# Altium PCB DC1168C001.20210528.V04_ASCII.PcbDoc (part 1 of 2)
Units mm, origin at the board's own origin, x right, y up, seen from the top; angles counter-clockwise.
Board outline 94.98 x 78.49 mm, 2 copper layers (Top Layer, Bottom Layer); 113 components, 100 nets, 347 pads, 214 vias.
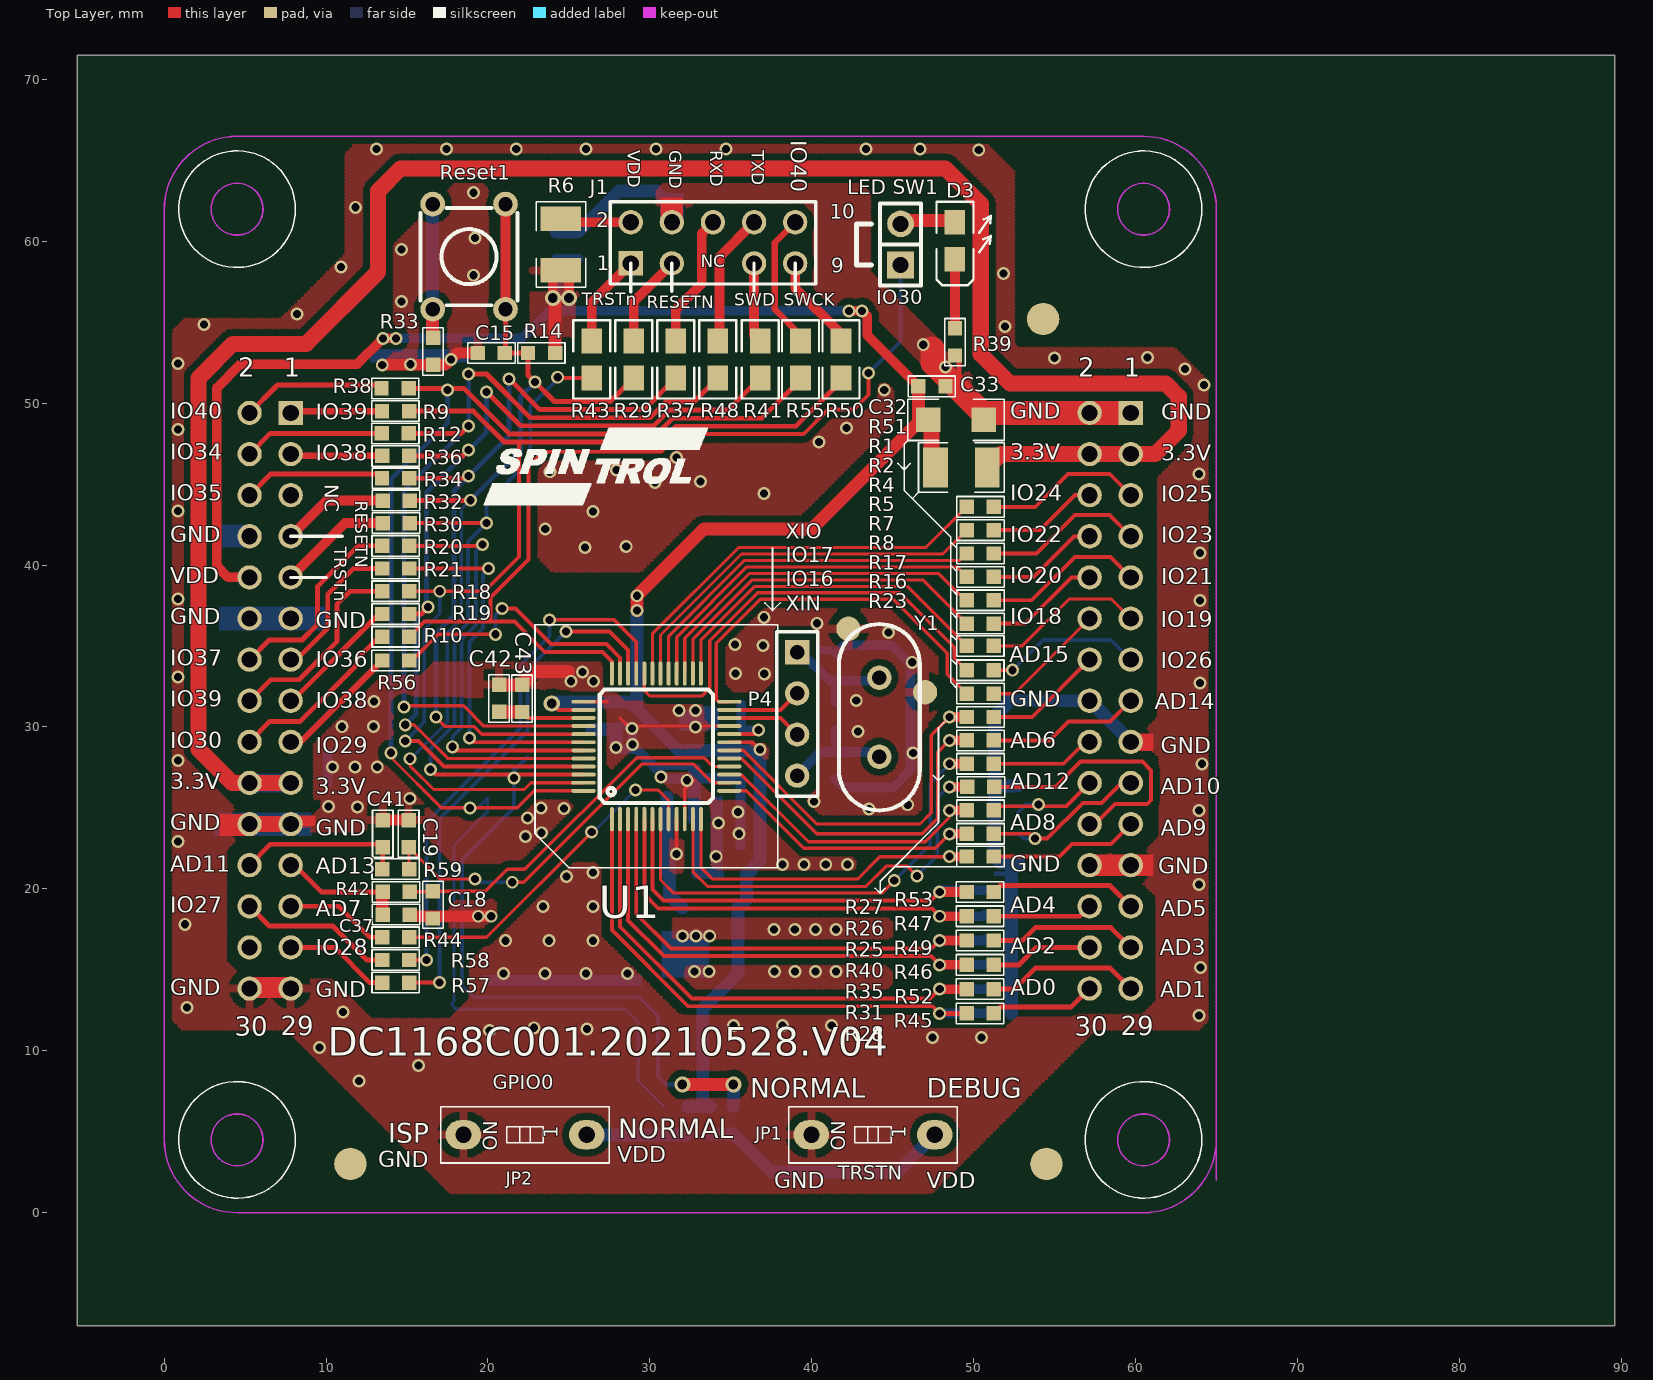
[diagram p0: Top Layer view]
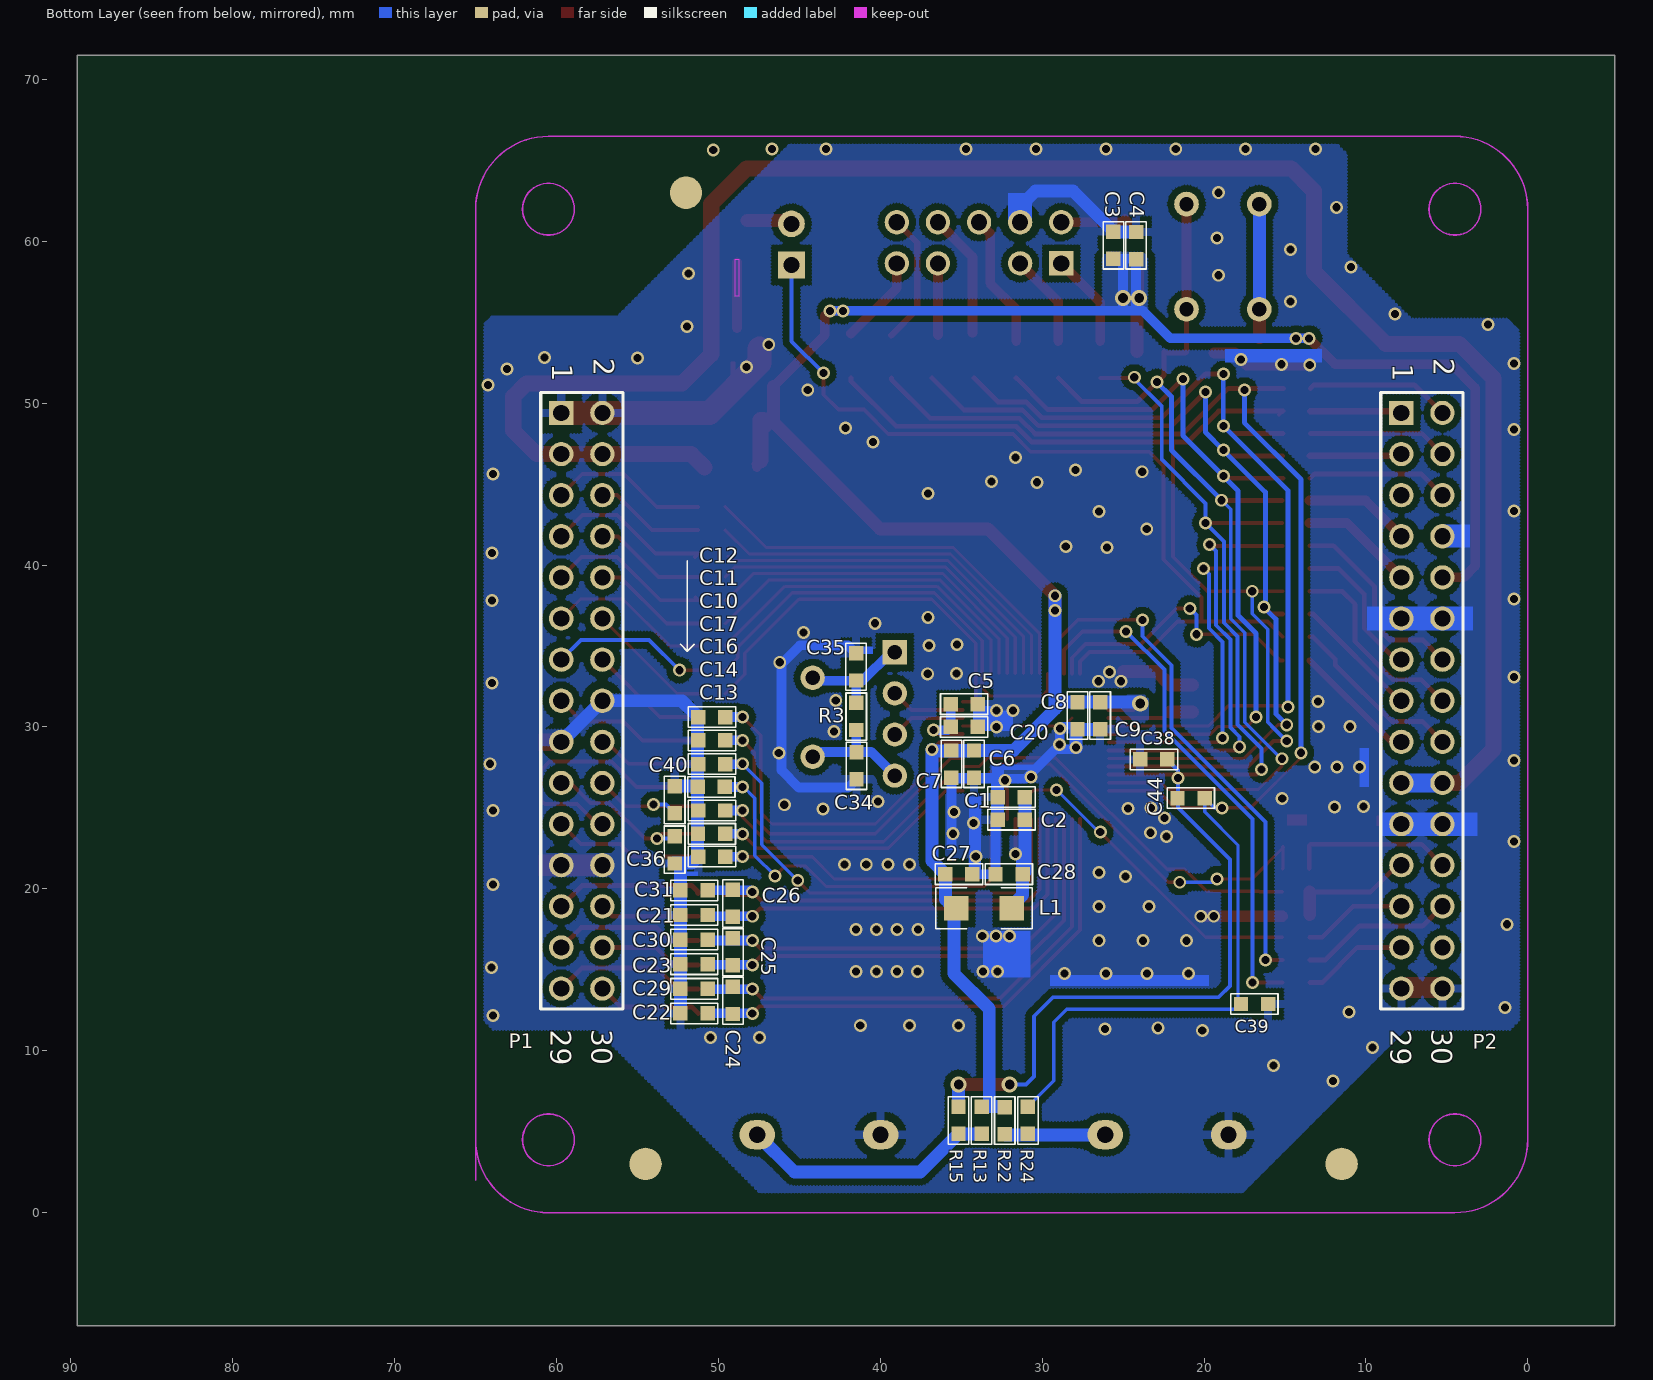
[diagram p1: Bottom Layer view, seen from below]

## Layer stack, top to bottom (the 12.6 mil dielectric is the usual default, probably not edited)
Top Solder: solder mask 0.0102, Solder Resist, Dk 3.5
Top Layer: signal copper 0.0356
Dielectric 1: dielectric 0.32, FR-4, Dk 4.8
Bottom Layer: signal copper 0.0356
Bottom Solder: solder mask 0.0102, Solder Resist, Dk 3.5

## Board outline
-5.372,-7 89.608,-7 89.608,71.49 -5.372,71.49

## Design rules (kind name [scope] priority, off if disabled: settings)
AssemblyTestPointUsage [All] p0: scope1count=1 scope1_0_kind=Board scope1_0_value=Board scope2count=1 scope2_0_kind=Board scope2_0_value=Board commentlength=0
AssemblyTestpoint [All] p0: scope1count=1 scope1_0_kind=Board scope1_0_value=Board scope2count=1 scope2_0_kind=Board scope2_0_value=Board commentlength=0
Clearance poly [All] p0 off: scope1count=1 scope1_0_kind=Board scope1_0_value=Board scope2count=1 scope2_0_kind=Board scope2_0_value=Board commentlength=48 gap=0.4 // Protel DXP Scope 2 Expression Was: InPolygon
Clearance xin [All] p0 off: scope1count=1 scope1_0_kind=Board scope1_0_value=Board scope2count=1 scope2_0_kind=Net scope2_0_value=XIN commentlength=48 gap=1 // Protel DXP Scope 1 Expression Was: InPolygon
Clearance xio [All] p0 off: scope1count=1 scope1_0_kind=Board scope1_0_value=Board scope2count=1 scope2_0_kind=Net scope2_0_value=XIO commentlength=48 gap=1 // Protel DXP Scope 1 Expression Was: InPolygon
Clearance [All] p0: scope1count=1 scope1_0_kind=Board scope1_0_value=Board scope2count=1 scope2_0_kind=Board scope2_0_value=Board commentlength=0 gap=0.2
Clearance poly [All vs InPolygon] p1: gap=0.4 ignorepadtopadclearanceinfootprint=FALSE except(0: Arc-Hole Track-Hole SMDPad-Hole THPad-Hole Via-Hole Fill-Hole Poly-Hole Region-Hole Text-Hole)
Clearance xio [InPolygon vs InNet('XIO')] p2: gap=1 ignorepadtopadclearanceinfootprint=FALSE except(0: Arc-Hole Track-Hole SMDPad-Hole THPad-Hole Via-Hole Fill-Hole Poly-Hole Region-Hole Text-Hole)
Clearance xin [InPolygon vs InNet('XIN')] p3: gap=1 ignorepadtopadclearanceinfootprint=FALSE except(0: Arc-Hole Track-Hole SMDPad-Hole THPad-Hole Via-Hole Fill-Hole Poly-Hole Region-Hole Text-Hole)
Clearance [All] p4: gap=0.2 ignorepadtopadclearanceinfootprint=FALSE except(0: Arc-Hole Track-Hole SMDPad-Hole THPad-Hole Via-Hole Fill-Hole Poly-Hole Region-Hole Text-Hole)
ComponentClearance [All] p0 off: scope1count=1 scope1_0_kind=Board scope1_0_value=Board scope2count=1 scope2_0_kind=Board scope2_0_value=Board commentlength=0 gap=0.254 collisioncheckmode=3
ComponentClearance [All] p1 off: gap=0.254 collisioncheckmode=3 verticalgap=0.254 showdistances=FALSE
DiffPairsRouting [All] p0: scope1count=1 scope1_0_kind=Board scope1_0_value=Board scope2count=1 scope2_0_kind=Board scope2_0_value=Board commentlength=0
DiffPairsRouting [All] p1: maxlimit=0.254 minlimit=0.24 mostfreqgap=0.254 toplayer_minwidth=0.2 toplayer_maxwidth=0.381 toplayer_prefwidth=5 bottomlayer_minwidth=0.2 bottomlayer_maxwidth=0.381 bottomlayer_prefwidth=5 maxuncoupledlength=12.7
FabricationTestPointUsage [All] p0: scope1count=1 scope1_0_kind=Board scope1_0_value=Board scope2count=1 scope2_0_kind=Board scope2_0_value=Board commentlength=0 valid=0 allowmultiple=FALSE
FabricationTestpoint [All] p0: scope1count=1 scope1_0_kind=Board scope1_0_value=Board scope2count=1 scope2_0_kind=Board scope2_0_value=Board commentlength=0 side=3 testpointundercomponent=TRUE minsize=1.016 maxsize=2.54 preferedsize=1.524 minholesize=0 maxholesize=1.016 preferedholesize=0.813 testpointgrid=0.025
FanoutControl Fanout_BGA [All] p0 off: scope1count=1 scope1_0_kind=Board scope1_0_value=Board scope2count=1 scope2_0_kind=Board scope2_0_value=Board commentlength=69 // Protel DXP Scope 1 Expression Was: IsBGA   Fanout_BGA (Default Rule)
FanoutControl Fanout_LCC [All] p0 off: scope1count=1 scope1_0_kind=Board scope1_0_value=Board scope2count=1 scope2_0_kind=Board scope2_0_value=Board commentlength=69 // Protel DXP Scope 1 Expression Was: IsLCC   Fanout_LCC (Default Rule)
FanoutControl Fanout_SOIC [All] p0 off: scope1count=1 scope1_0_kind=Board scope1_0_value=Board scope2count=1 scope2_0_kind=Board scope2_0_value=Board commentlength=71 // Protel DXP Scope 1 Expression Was: IsSOIC   Fanout_SOIC (Default Rule)
FanoutControl Fanout_Small [All] p0 off: scope1count=1 scope1_0_kind=Board scope1_0_value=Board scope2count=1 scope2_0_kind=Board scope2_0_value=Board commentlength=84 // Protel DXP Scope 1 Expression Was: (CompPinCount < 5)   Fanout_Small (Default Rule)
FanoutControl Fanout_Default [All] p0: scope1count=1 scope1_0_kind=Board scope1_0_value=Board scope2count=1 scope2_0_kind=Board scope2_0_value=Board commentlength=30 // Fanout_Default (Default Rule)
Height [All] p0 off: scope1count=1 scope1_0_kind=Board scope1_0_value=Board scope2count=1 scope2_0_kind=Board scope2_0_value=Board commentlength=0
Height [All] p1 off: minheight=0 maxheight=25.4 prefheight=12.7
HoleSize [All] p0: scope1count=1 scope1_0_kind=Board scope1_0_value=Board scope2count=1 scope2_0_kind=Board scope2_0_value=Board commentlength=0 absolutevalues=TRUE maxlimit=5 minlimit=0.025 maxpercent=80.000 minpercent=20.000
HoleSize [All] p1: absolutevalues=TRUE maxlimit=5 minlimit=0.025 maxpercent=80.000 minpercent=20.000
HoleToHoleClearance [All] p0 off: scope1count=1 scope1_0_kind=Board scope1_0_value=Board scope2count=1 scope2_0_kind=Board scope2_0_value=Board commentlength=0
HoleToHoleClearance [All] p1 off: gap=0.254 allowstackedmicrovias=FALSE
LayerPairs [All] p0: scope1count=1 scope1_0_kind=Board scope1_0_value=Board scope2count=1 scope2_0_kind=Board scope2_0_value=Board commentlength=0 enforce=FALSE
LayerPairs [All] p1: enforce=FALSE
MinimumSolderMaskSliver [All] p0 off: scope1count=1 scope1_0_kind=Board scope1_0_value=Board scope2count=1 scope2_0_kind=Board scope2_0_value=Board commentlength=0
MinimumSolderMaskSliver [All] p1 off: minsoldermaskwidth=0.254
NetAntennae [All] p0: scope1count=1 scope1_0_kind=Board scope1_0_value=Board scope2count=1 scope2_0_kind=Board scope2_0_value=Board commentlength=0
PasteMaskExpansion [All] p0 off: scope1count=1 scope1_0_kind=Board scope1_0_value=Board scope2count=1 scope2_0_kind=Board scope2_0_value=Board commentlength=0 expansion=0
PasteMaskExpansion [All] p1 off: expansion=0
PlaneClearance [All] p0: scope1count=1 scope1_0_kind=Board scope1_0_value=Board scope2count=1 scope2_0_kind=Board scope2_0_value=Board commentlength=0 clearance=0.508
PlaneConnect [All] p0: scope1count=1 scope1_0_kind=Board scope1_0_value=Board scope2count=1 scope2_0_kind=Board scope2_0_value=Board commentlength=0 planeconnectstyle=Direct reliefexpansion=0.508 reliefentries=4 reliefconductorwidth=0.254 reliefairgap=0.254
PlaneConnect [All] p1: planeconnectstyle=Direct reliefexpansion=0.508 reliefentries=4 reliefconductorwidth=0.254 reliefairgap=0.254
PolygonConnect [All] p0 off: scope1count=1 scope1_0_kind=Board scope1_0_value=Board scope2count=1 scope2_0_kind=Board scope2_0_value=Board commentlength=63 connectstyle=Relief reliefconductorwidth=0.5 reliefentries=4 polygonreliefangle="90 Angle" // Protel DXP Scope 2 Expression Was: (InPadClass('All Pads'))
PolygonConnect PolygonConnect_1 [All] p0: scope1count=1 scope1_0_kind=Board scope1_0_value=Board scope2count=1 scope2_0_kind=Board scope2_0_value=Board commentlength=0 connectstyle=Direct reliefconductorwidth=0.254 reliefentries=4 polygonreliefangle="90 Angle"
PolygonConnect [All vs (InPadClass('All Pads'))] p1: connectstyle=Relief reliefconductorwidth=0.5 reliefentries=4 polygonreliefangle="90 Angle" airgapwidth=0.5
PolygonConnect PolygonConnect_1 [All] p2: connectstyle=Direct reliefconductorwidth=0.254 reliefentries=4 polygonreliefangle="90 Angle" airgapwidth=0.254
RoutingCorners [All] p0: scope1count=1 scope1_0_kind=Board scope1_0_value=Board scope2count=1 scope2_0_kind=Board scope2_0_value=Board commentlength=0 cornerstyle=45-Degree minsetback=2.54 maxsetback=2.54
RoutingLayers [All] p0: scope1count=1 scope1_0_kind=Board scope1_0_value=Board scope2count=1 scope2_0_kind=Board scope2_0_value=Board commentlength=0 top layer=Automatic bottom layer=Automatic
RoutingPriority [All] p0: scope1count=1 scope1_0_kind=Board scope1_0_value=Board scope2count=1 scope2_0_kind=Board scope2_0_value=Board commentlength=0
RoutingTopology [All] p0: scope1count=1 scope1_0_kind=Board scope1_0_value=Board scope2count=1 scope2_0_kind=Board scope2_0_value=Board commentlength=0 topology=Shortest
RoutingVias [All] p0: scope1count=1 scope1_0_kind=Board scope1_0_value=Board scope2count=1 scope2_0_kind=Board scope2_0_value=Board commentlength=0 holewidth=0.8 width=0.5 viastyle="Through Hole" minholewidth=0.3 minwidth=0.3 maxholewidth=6 maxwidth=3
RoutingVias [All] p1: holewidth=0.8 width=0.5 viastyle="Through Hole" minholewidth=0.3 minwidth=0.3 maxholewidth=6 maxwidth=3
ShortCircuit [All] p0: scope1count=1 scope1_0_kind=Board scope1_0_value=Board scope2count=1 scope2_0_kind=Board scope2_0_value=Board commentlength=0 allowed=FALSE
SilkToBoardRegionClearance [All] p0 off: scope1count=1 scope1_0_kind=Board scope1_0_value=Board scope2count=1 scope2_0_kind=Board scope2_0_value=Board commentlength=0
SilkToBoardRegionClearance [All] p1 off:
SilkToSilkClearance [All] p0 off: scope1count=1 scope1_0_kind=Board scope1_0_value=Board scope2count=1 scope2_0_kind=Board scope2_0_value=Board commentlength=0
SilkToSilkClearance [All] p1 off: silktosilkclearance=0
SilkToSolderMaskClearance [All] p0 off: scope1count=1 scope1_0_kind=Board scope1_0_value=Board scope2count=1 scope2_0_kind=Board scope2_0_value=Board commentlength=44 // Protel DXP Scope 1 Expression Was: IsPad
SilkToSolderMaskClearance [IsPad] p1 off: minsilkscreentomaskgap=0 clearancetoexposedcopper=TRUE
SolderMaskExpansion [All] p0 off: scope1count=1 scope1_0_kind=Board scope1_0_value=Board scope2count=1 scope2_0_kind=Board scope2_0_value=Board commentlength=0 expansion=0.102
SolderMaskExpansion [All] p1 off: expansion=0.102 istentingtop=FALSE
UnRoutedNet [All] p0: scope1count=1 scope1_0_kind=Board scope1_0_value=Board scope2count=1 scope2_0_kind=Board scope2_0_value=Board commentlength=0
UnpouredPolygon [All] p0: scope1count=1 scope1_0_kind=Board scope1_0_value=Board scope2count=1 scope2_0_kind=Board scope2_0_value=Board commentlength=0
Width [All] p0: scope1count=1 scope1_0_kind=Board scope1_0_value=Board scope2count=1 scope2_0_kind=Board scope2_0_value=Board commentlength=0 maxlimit=5 minlimit=0.2 preferedwidth=0.24
Width [All] p1: maxlimit=5 minlimit=0.2 preferedwidth=0.24 minimp=50.000000 maximp=50.000000 favimp=50.000000
18 further rules are at their usual default settings.

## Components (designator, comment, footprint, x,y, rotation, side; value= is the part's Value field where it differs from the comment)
C1 "4.7uF/10V" 0603 31.91,25.662 r0 bottom
C2 "100nF" 0603 31.91,24.265 r0 bottom
C3 "100nF" 0603 25.596,59.76 r90 bottom
C4 "4.7uF/10V" 0603 24.196,59.735 r270 bottom
C5 "100nF" 0603 34.808,31.4 r180 bottom
C6 "4.7uF/10V" 0603 34.208,27.7 r270 bottom
C7 "100nF" 0603 35.608,27.7 r270 bottom
C8 "100nF" 0603 27.819,30.69 r270 bottom
C9 "4.7uF/10V" 0603 26.414,30.69 r270 bottom
C10 "100pF±10%" 0603 50.408,27.7 r0 bottom
C11 "100pF±10%" 0603 50.41,29.165 r0 bottom
C12 "100pF±10%" 0603 50.41,30.605 r0 bottom
C13 "100pF±10%" 0603 50.41,21.985 r0 bottom
C14 "100pF±10%" 0603 50.42,23.395 r0 bottom
C15 "1uF/6.3V" 0603 20.208,53.1 r180 top
C16 "100pF±10%" 0603 50.41,24.835 r0 bottom
C17 "100pF±10%" 0603 50.45,26.295 r0 bottom
C18 "100pF±10%" 0603 16.6,19 r270 top
C19 "100pF±10%" 0603 15.1,23.4 r90 top
C20 "4.7uF/10V" 0603 34.808,30 r180 bottom
C21 "100pF±10%" 0603 51.508,18.38 r0 bottom
C22 "100pF±10%" 0603 51.508,12.3 r0 bottom
C23 "100pF±10%" 0603 51.508,15.34 r0 bottom
C24 "22pF±10%" 0603 49.108,13.1 r90 bottom
C25 "22pF±10%" 0603 49.108,16.1 r90 bottom
C26 "22pF±10%" 0603 49.108,19.1 r90 bottom
C27 "100nF" 0603 35.146,20.9 r0 bottom
C28 "100nF" 0603 32.046,20.9 r180 bottom
C29 "100pF±10%" 0603 51.508,13.82 r0 bottom
C30 "100pF±10%" 0603 51.508,16.86 r0 bottom
C31 "100pF±10%" 0603 51.508,19.9 r0 bottom
C32 "47uF/10V" 1206 47.2,48.965 r0 top
C33 "100nF" 0603 47.43,51.04 r0 top
C34 "22pF不焊" 0603 41.466,27.605 r90 bottom
C35 "22pF不焊" 0603 41.496,33.705 r270 bottom
C36 "100pF±10%" 0603 52.7,22.4 r270 bottom
C37 "100pF±10%" 0603 14.33,18.4 r0 top
C38 "100nF" 0603 23.107,27.99 r0 bottom
C39 "100nF" 0603 16.88,12.88 r180 bottom
C40 "100pF±10%" 0603 52.7,25.5 r90 bottom
C41 "100pF±10%" 0603 13.5,23.4 r90 top
C42 "4.7uF/10V" 0603 20.69,31.77 r90 top
C43 "100nF" 0603 22.11,31.76 r90 top
C44 "4.7uF/10V" 0603 20.8,25.6 r180 bottom (schematic designator C4)
D3 "绿0805" led0805 48.85,60.025 r270 top
J1 "双排插针2.54*5" HDR2X5 28.82,58.635 r0 top locked
JP1 "DSIC01LH-P" S7.62*1 47.6,4.8 r180 top
JP2 "DSIC01LH-P" S7.62*1 26.1,4.8 r180 top
L1 "1.5uH" 1206 35.308,18.8 r180 bottom
"LED SW1" "单排插针2.54*2" CON2 45.49,58.535 r180 top
P1 "双排针2.54*15插针" HDR2X15 59.71,49.395 r270 bottom locked
P2 "双排针2.54*15插针" HDR2X15 7.81,49.395 r270 bottom locked
P4 "Header 4" HDR1X4 39.1,34.61 r270 top (schematic designator P1)
R1 "100R" 0603 50.41,43.595 r180 top
R2 "100R" 0603 50.41,42.152 r180 top
R3 "1M不焊" 0603 41.486,30.648 r90 bottom
R4 "100R" 0603 50.41,40.709 r180 top
R5 "100R" 0603 50.41,39.266 r180 top
R6 "0.1R  1/2W" 1210 24.508,58.2 r90 top
R7 "100R" 0603 50.41,37.824 r180 top
R8 "100R" 0603 50.41,36.381 r180 top
R9 "100R" 0603 14.288,49.51 r0 top
R10 "100R" 0603 14.31,35.569 r0 top
R12 "100R" 0603 14.268,48.13 r180 top
R13 "2k" 0603 33.74,5.7 r90 bottom
R14 "4.7K" 0603 23.308,53.1 r0 top
R15 "2K" 0603 35.17,5.7 r90 bottom
R16 "100R" 0603 50.408,33.5 r180 top
R17 "100R" 0603 50.408,35 r180 top
R18 "100R" 0603 14.31,38.377 r0 top
R19 "100R" 0603 14.31,36.973 r0 top
R20 "100R" 0603 14.31,41.186 r0 top
R21 "100R" 0603 14.31,39.782 r0 top
R22 "2k" 0603 32.31,5.675 r270 bottom
R23 "100R" 0603 50.41,32.052 r180 top
R24 "2K" 0603 30.88,5.7 r90 bottom
R25 "100R" 0603 50.41,27.724 r180 top
R26 "100R" 0603 50.41,29.166 r180 top
R27 "100R" 0603 50.41,30.609 r180 top
R28 "100R" 0603 50.41,21.995 r180 top
R29 "20R" 0805 29.008,52.7 r270 top
R30 "100R" 0603 14.328,42.59 r0 top
R31 "100R" 0603 50.41,23.398 r180 top
R32 "100R" 0603 14.328,43.98 r0 top
R33 "100R" 0603 16.608,53.2 r90 top
R34 "100R" 0603 14.288,45.36 r180 top
R35 "100R" 0603 50.41,24.845 r180 top
R36 "100R" 0603 14.308,46.74 r0 top
R37 "20R" 0805 31.608,52.7 r90 top
R38 "100R" 0603 14.258,50.91 r180 top
R39 "1k" 0603 48.85,53.78 r90 top
R40 "100R" 0603 50.45,26.295 r180 top
R41 "20R" 0805 36.808,52.7 r270 top
R42 "100R" 0603 14.33,19.807 r0 top
R43 "20R" 0805 26.408,52.7 r270 top
R44 "100R" 0603 14.308,17 r0 top
R45 "100R" 0603 50.408,12.3 r0 top
R46 "100R" 0603 50.408,15.3 r0 top
R47 "100R" 0603 50.408,18.3 r0 top
R48 "20R" 0805 34.208,52.7 r90 top
R49 "100R" 0603 50.408,16.8 r0 top
R50 "20R" 0805 41.808,52.7 r270 top
R51 "0.1R 1/2W" 1210 50.85,46.025 r180 top (schematic designator R39)
R52 "100R" 0603 50.408,13.8 r0 top
R53 "100R" 0603 50.408,19.8 r0 top
R55 "20R" 0805 39.308,52.7 r90 top
R56 "100R" 0603 14.3,34.1 r0 top
R57 "100R" 0603 14.308,14.2 r0 top
R58 "100R" 0603 14.308,15.6 r0 top
R59 "100R" 0603 14.308,21.21 r0 top
Reset1 "插件按键6*6*5" SW-TACT-6X6 18.833,59.048 r270 top
U1 "SPC1168" PQFP48 30.408,28.8 r90 top locked
Y1 "OSC32MHz不焊" OSC 44.176,30.595 r90 top locked

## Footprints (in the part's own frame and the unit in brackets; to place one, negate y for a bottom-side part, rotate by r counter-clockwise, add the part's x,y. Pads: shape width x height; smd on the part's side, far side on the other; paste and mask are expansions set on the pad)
0603 [mil]
  rect 35x35 smd: 1(-33,0) 2(33,0)
  silkscreen extent -58,-25 57,25
0805 [mil]
  rect 60x50 smd: 1(-45,0) 2(45,0)
  silkscreen extent -95,-45 95,45
1206 [mil]
  rect 60x60 smd: 1(0,0) 2(135,0)
  silkscreen extent -50,-50 185,50
1210 [mm]
  rect 1.524x2.5 smd: 1(0,0) 2(3.2,0)
  silkscreen extent -1.05,-1.53 4.25,1.53
CON2 [mil]
  rect 65x65 hole 39.37: 1(0,0)
  round 65 hole 39.37: 2(0,-100)
  silkscreen extent -50,-150 50,50
HDR1X4 [mm] "Connector; Header; 4 Position"
  rect 1.5x1.5 hole 0.9: 1(0,0)
  round 1.5 hole 0.9: 2(2.54,0) 3(5.08,0) 4(7.62,0)
  silkscreen extent -1.27,-1.27 8.89,1.27
HDR2X5 [mm] "Connector; Header; 5x2 Position"
  rect 1.5x1.5 hole 1: 1(0,0)
  round 1.5 hole 1: 2(0,2.54) 3(2.54,0) 4(2.54,2.54) 6(5.08,2.54) 7(7.62,0) 8(7.62,2.54) 9(10.16,0) 10(10.16,2.54)
  silkscreen extent -1.27,-1.27 11.43,3.81
HDR2X15 [mm] "Connector; Header; 15x2 Position"
  rect 1.5x1.5 hole 1: 1(0,0)
  round 1.5 hole 1: 2(0,2.54) 3(2.54,0) 4(2.54,2.54) 5(5.08,0) 6(5.08,2.54) 7(7.62,0) 8(7.62,2.54) 9(10.16,0) 10(10.16,2.54) 11(12.7,0) 12(12.7,2.54) 13(15.24,0) 14(15.24,2.54) 15(17.78,0) 16(17.78,2.54) 17(20.32,0) 18(20.32,2.54) 19(22.86,0) 20(22.86,2.54) 21(25.4,0) 22(25.4,2.54) 23(27.94,0) 24(27.94,2.54) 25(30.48,0) 26(30.48,2.54) 27(33.02,0) 28(33.02,2.54) 29(35.56,0) 30(35.56,2.54)
  silkscreen extent -1.27,-1.27 36.83,3.81
led0805 [mil]
  rect 60x50 smd: 1(-45,0) 2(45,0)
  Bottom Layer keep-out region: 134.82,-4.48 134.82,4.38 44.82,4.38 44.82,-4.48
  silkscreen extent -95,-45 108,88
OSC [mm] "CRYSTAL 32.0000MHZ 20PF T/H"
  round 1.5 hole 0.9: 1(-2.44,0) 2(2.44,0)
  silkscreen extent -5.75,-2.5 5.75,2.5
PQFP48 [mm]
  oval 1.5x0.24 smd: 1(-4.5,2.75) 2(-4.5,2.25) 3(-4.5,1.75) 4(-4.5,1.25) 5(-4.5,0.75) 6(-4.5,0.25) 7(-4.5,-0.25) 8(-4.5,-0.75) 9(-4.5,-1.25) 10(-4.5,-1.75) 11(-4.5,-2.25) 12(-4.5,-2.75) 25(4.5,-2.75) 26(4.5,-2.25) 27(4.5,-1.75) 28(4.5,-1.25) 29(4.5,-0.75) 30(4.5,-0.25) 31(4.5,0.25) 32(4.5,0.75) 33(4.5,1.25) 34(4.5,1.75) 35(4.5,2.25) 36(4.5,2.75)
  oval 0.24x1.5 smd: 13(-2.75,-4.5) 14(-2.25,-4.5) 15(-1.75,-4.5) 16(-1.25,-4.5) 17(-0.75,-4.5) 18(-0.25,-4.5) 19(0.25,-4.5) 20(0.75,-4.5) 21(1.25,-4.5) 22(1.75,-4.5) 23(2.25,-4.5) 24(2.75,-4.5) 37(2.75,4.5) 38(2.25,4.5) 39(1.75,4.5) 40(1.25,4.5) 41(0.75,4.5) 42(0.25,4.5) 43(-0.25,4.5) 44(-0.75,4.5) 45(-1.25,4.5) 46(-1.75,4.5) 47(-2.25,4.5) 48(-2.75,4.5)
  silkscreen extent -7.5,-7.5 7.5,7.5
S7.62*1 [mm]
  oval 2.2x1.8 hole 1: 1(0,0) 2(7.62,0)
  silkscreen extent -1.4,-1.74 9.02,1.74
SW-TACT-6X6 [mil]
  round 60 hole 35: 1(-127.95,88.58) 1(127.95,88.58) 2(-127.95,-88.58) 2(127.95,-88.58)
  silkscreen extent -118,-118 118,118

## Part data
C1 C2 C4 C5 C6 C7 C8 C9 C10 C11 C12 C13 C14 C16 C17 C18 C19 C20 C21 C22 C23 C24 C25 C26 C29 C30 C31 C36 C37 C38 C39 C40 C41 C42 C43 C44: library part CAP-CC(SMD), "Capacitor"
C3: library part CAP-CC, "Capacitor"
C15 C32 C33: library part Cap, "Capacitor"
C27 C28: library part CAP-CC
C34 C35: library part "Capacitor Unpolarized", "CAP CER 20PF 10V X7R 0603"
D3: library part LED2, "FC-2012UGK-520D5"
J1: library part CON10_BI, "ISP SOCKET"
JP1 JP2: library part SW-2
L1: library part INDUCTOR1
"LED SW1": library part Jumper, "Jumper Wire"
P1 P2: library part "Header 15X2", "Header, 15-Pin, Dual row"
P4: "Header, 4-Pin"
R1 R2 R4 R5 R6 R7 R8 R9 R10 R12 R15 R16 R17 R18 R19 R20 R21 R23 R24 R25 R26 R27 R28 R29 R30 R31 R32 R34 R35 R36 R37 R38 R40 R41 R42 R43 R44 R45 R46 R47 R48 R49 R50 R51 R52 R53 R55 R56 R57 R58 R59: library part RES(SMD)
R3: library part Resistor, "Resistor"
R13 R14 R22 R33 R39: library part Res1, "Resistor"
Reset1: library part SW-PB, "Switch"
U1: library part GECKO, "32-bit ARM CM4 MCU"
Y1: library part OSC32MHz, "CRYSTAL 32.0000MHZ 20PF T/H"

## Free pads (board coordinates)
  round 2 smd: 1(11.5,3) 1(54.3,55.2) 1(54.5,3)
  round 2 smd far side: 1(11.5,3) 1(52,63) 1(54.5,3)
  round 1.5 smd: 1(47,32.14) 2(42.27,36.06)

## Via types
v1: diameter 0.8, hole 0.5, Top Layer to Bottom Layer, tented both sides, 209 vias
v2: diameter 1, hole 0.6, Top Layer to Bottom Layer, tented both sides, 5 vias

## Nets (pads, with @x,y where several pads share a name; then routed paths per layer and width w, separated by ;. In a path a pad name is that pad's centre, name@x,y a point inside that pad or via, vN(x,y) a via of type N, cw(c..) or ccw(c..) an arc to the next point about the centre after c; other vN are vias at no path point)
+3.3V: P1.3 P1.4 P2.19 P2.20 R51.1 | length 127
  Top Layer w1: P2.19@7.81,26.535 P2.20@5.27,26.535 4.2,26.535 2.118,28.617 2.118,51.54 4.238,53.66 8.768,53.66 13.208,58.1 13.208,63.1 14.608,64.5 48.25,64.5 50.44,62.31 50.44,53.02 52.24,51.22 61.855,51.22 62.67,50.405 62.67,48.305 61.22,46.855 P1.3@59.71,46.855 P1.4@57.17,46.855 51.68,46.855 R51.1@50.85,46.025
  Bottom Layer w1.2: P2.20@5.27,26.535 P2.19@7.81,26.535
ADC6: C10.1 R25.2 U1.7 | length 29.7
  Top Layer w0.2: U1.7@30.658,24.3 30.658,20.54 31.468,19.73 44.33,19.73 v1(45.1,20.5)
  Top Layer w0.6: v1@48.424,27.724 v1(48.51,27.724) R25.2@49.572,27.724
  Bottom Layer w0.2: v1(45.1,20.5) 47.33,22.73 47.33,26.52 v1@48.51,27.7
  Bottom Layer w0.6: v1@48.51,27.7 C10.1@49.57,27.7
ADC7: R44.2 U1.8 | length 21.2
  Top Layer w0.2: R44.2@15.146,17 19.908,17 v1(26.408,23.5) ; v1(29.108,26.1) 30.508,26.1 31.158,25.45 U1.8@31.158,24.3
  Bottom Layer w0.2: v1@26.458,23.45 v1(29.108,26.1)
ADC8: C17.1 R40.2 U1.11 | length 26.9
  Top Layer w0.2: U1.11@32.658,24.3 32.658,21.06 33.578,20.14 43.34,20.14 44.6,21.4 45.9,21.4 v1(46.5,20.8)
  Top Layer w0.6: v1@48.448,26.295 R40.2@49.612,26.295
  Bottom Layer w0.2: v1(46.5,20.8) 47.75,22.05 47.75,25.587 v1@48.448,26.285
  Bottom Layer w0.6: v1@48.448,26.285 C17.1@49.612,26.285
  other v1: 48.51,26.28
ADC9: C13.1 R28.2 U1.12 | length 21.8
  Top Layer w0.2: U1.12@33.158,24.3 33.158,21.32 33.878,20.6 42.828,20.6 44.208,21.98 v1@48.408,21.98 ; R28.2@49.267,22.3 R28.2@49.572,21.995
  Top Layer w0.6: v1@48.408,21.98 R28.2@49.557,21.98
  Bottom Layer w0.6: v1@48.408,21.985 C13.1@49.572,21.985
  other v1: 48.51,21.98
ADC10: C14.1 R31.2 U1.13 | length 17.7
  Top Layer w0.2: U1.13@34.908,26.05 35.95,26.05 39.5,22.5 47.62,22.5 v1@48.518,23.398
  Top Layer w0.6: v1@48.518,23.398 R31.2@49.572,23.398
  Bottom Layer w0.6: v1@48.418,23.395 C14.1@49.582,23.395
  other v1: 48.51,23.39
ADC11: C19.1 R59.2 U1.14 | length 25.7
  Top Layer w0.2: C19.1@15.1,22.562 C19.1@15.116,22.546 ; C19.1@15.116,22.62 C19.1@15.116,22.546 ; R59.2@15.146,21.23 15.116,21.26 C19.1@15.116,22.546 ; C19.1@15.146,22.6 C19.1@15.146,22.516 ; v1(19.2,20.6) 17.062,20.6 C19.1@15.146,22.516 ; v1(21.5,20.4) 22.2,20.4 29.5,27.7 32.7,27.7 33.85,26.55 U1.14@34.908,26.55 ; C19.1@15.116,22.546 C19.1@15.146,22.516
  Bottom Layer w0.2: v1(19.2,20.6) 19.4,20.4 v1(21.5,20.4)
ADC12: C16.1 R35.2 U1.15 | length 18.6
  Top Layer w0.2: U1.15@34.908,27.05 35.65,27.05 39.8,22.9 47.01,22.9 48.51,24.4 v1(48.51,24.83)
  Top Layer w0.6: v1(48.51,24.83) 48.525,24.845 R35.2@49.572,24.845
  Bottom Layer w0.6: v1@48.408,24.835 C16.1@49.572,24.835
ADC13: C18.1 R42.2 U1.16 | length 23.4
  Top Layer w0.2: R42.2@15.168,19.807 16.569,19.807 C18.1@16.6,19.838 19.838,19.838 21.2,21.2 22.282,21.2 29.182,28.1 33.35,28.1 33.9,27.55 U1.16@34.908,27.55
ADC14: C11.1 R26.2 U1.17 | length 22.5
  Top Layer w0.2: U1.17@34.908,28.05 35.65,28.05 40.3,23.4 46.83,23.4 47.78,24.35 47.78,28.436 v1(48.51,29.166)
  Top Layer w0.6: v1(48.51,29.166) R26.2@49.572,29.166 R26.2@49.658,29.166
  Bottom Layer w0.6: v1(48.51,29.166) C11.1@49.57,29.166
ADC15: C12.1 R27.2 U1.18 | length 23.2
  Top Layer w0.2: U1.18@34.908,28.55 35.758,28.55 40.308,24 46.69,24 47.38,24.69 47.38,29.47 v1(48.51,30.6)
  Top Layer w0.6: v1@48.51,30.609 R27.2@49.572,30.609
  Bottom Layer w0.6: v1@48.408,30.605 C12.1@49.572,30.605
ADC_7: P2.25 R44.1 | length 6.5
  Top Layer w0.3: P2.25@7.81,18.915 10.793,18.915 12.708,17 R44.1@13.47,17
ADC_11: C41.1 P2.24 R59.1 | length 10.2
  Top Layer w0.3: P2.24@5.27,21.455 6.56,22.745 13.417,22.745 13.5,22.662 R59.1@13.5,21.24
ADC_13: C37.1 P2.23 R42.1 | length 7.8
  Top Layer w0.3: P2.23@7.81,21.455 8.053,21.455 9.701,19.807 13.47,19.807 R42.1@13.492,19.807 ; C37.1@13.47,18.4 C37.1@13.492,18.422
  Top Layer w0.8: C37.1@13.47,18.4 R42.1@13.47,19.807
DC_BUS: P1.18 R25.1 | length 6.2
  Top Layer w0.24: R25.1@51.248,27.724 55.549,27.724 P1.18@56.9,29.075
DIR: P1.11 R17.1 | length 10.2
  Top Layer w0.2: R17.1@51.246,35 53.008,35 55.908,37.9 58.505,37.9 P1.11@59.71,36.695
GND: C1.2 C2.2 C3.2 C4.1 C5.2 C6.2 C7.2 C8.2 C9.2 C10.2 C11.2 C12.2 C13.2 C14.2 C15.2 C16.2 C17.2 C18.2 C19.2 C20.2 C21.2 C22.2 C23.2 C27.1 C28.1 C29.2 C30.2 C31.2 C32.2 C33.2 C34.1 C35.1 C36.2 C37.2 C38.2 C39.2 C40.2 C41.2 C42.2 C43.2 J1.4 JP1.2 JP2.2 P1.1 P1.2 P1.16 P1.17 P1.23 P1.24 P2.8 P2.11 P2.12 P2.21 P2.22 P2.29 P2.30 pad.1@47,32.14 pad.2 R33.1 R39.1 U1.10 U1.21 U1.37 | length 125.8
  Top Layer w0.2: 28.158,30.55 28.658,30.05 U1.21@34.908,30.05
  Top Layer w0.24: U1.37@25.908,31.55 27.37,31.55 ; U1.10@32.158,24.3 32.158,26.15 32.708,26.7
  Top Layer w0.7: P2.21@7.81,23.995 P2.21@7.815,24 ; v1(13.47,52.362) R33.1@16.608,52.362 17.37,52.362 v1(17.708,52.7) 18.108,53.1 C15.2@19.37,53.1 ; C37.2@15.168,18.3 v1(20.2,18.3)
  Top Layer w0.8: C42.2@20.7,32.598 C43.2@22.11,32.598 22.932,33.42 24.98,33.42
  Top Layer w1: P2.22@5.27,23.995 P2.21@7.81,23.995
  Top Layer w1.5: 47.46,53.36 47.46,52.487 50.552,49.395 P1.2@57.17,49.395 P1.1@59.71,49.395
  Bottom Layer w0.6: v1@27.819,28.611 v1@28.908,28.611 ; v1(28.908,29.9) v1@28.908,28.611 ; C2.2@32.748,24.265 32.884,24.129 C28.1@32.884,20.9 C27.1@34.308,20.9 ; 32.77,26.862 C6.2@34.208,26.862 C7.2@35.608,26.862 35.546,26.8 32.748,26.8 31.008,26.8 29.197,28.611 v1@28.908,28.611 ; v1(32.808,31) C5.2@33.57,31 ; C20.2@33.97,30 C5.2@33.97,31 ; C34.1@41.466,26.767 41.973,26.26 45.038,26.26 46.103,27.325 46.103,33.887 44.956,35.035 41.987,35.035 C35.1@41.496,34.543
  Bottom Layer w0.8: C4.1@24.196,60.573 25.571,60.573 C3.2@25.596,60.599 28.097,63.1 30.408,63.1 31.36,62.148 J1.4@31.36,61.175 ; C9.2@26.414,29.852 C8.2@27.819,29.852 ; v1(27.908,28.73) C8.2@27.908,29.841 ; C2.2@32.748,24.265 C1.2@32.748,25.662 32.748,26.8 ; C13.2@51.248,21.985 51.633,21.6 C36.2@52.346,21.6 ; C13.2@51.288,22.025 C17.2@51.288,26.295 51.288,30.565 C12.2@51.248,30.605 52.258,31.615 P1.16@57.17,31.615 P1.17@59.71,29.075 ; C17.2@51.331,26.338 C40.2@52.7,26.338 ; C22.2@52.346,12.3 C29.2@52.346,13.82 C23.2@52.346,15.34 C30.2@52.346,16.86 C21.2@52.346,18.38 C31.2@52.346,19.9 C36.2@52.346,21.6 ; C36.2@52.8,21.6 C36.2@52.346,21.6
  other v1: 12.04,8.125 15.71,9.075 9.598,10.2 47.464,10.81 50.498,10.81 20.107,11.24 26.118,11.33 22.848,11.41 35.168,11.55 38.202,11.55 41.236,11.55 63.93,12.175 11.04,12.375 1.41,12.665 20.968,14.77 23.518,14.77 26.068,14.77 28.618,14.77 32.748,14.89 33.648,14.89 37.708,14.89 38.974,14.89 40.241,14.89 41.507,14.89 64.008,15.14 21.088,16.79 23.778,16.79 26.488,16.79 32.018,17.07 32.858,17.07 33.698,17.07 37.678,17.49 38.954,17.49 40.231,17.49 41.507,17.49 1.29,17.805 19.4,18.3 23.408,18.9 26.488,18.9 63.938,20.27 24.848,20.76 26.488,21.01 38.2,21.499 39.533,21.499 40.867,21.499 42.2,21.499 34.1,22 0.848,22.92 22.318,23.22 35.5,23.4 23.307,23.46 34.248,24.06 22.438,24.37 35.448,24.73 63.93,24.844 43.55,24.93 24.708,24.95 23.278,24.99 11.938,25.05 10.138,25.08 45.93,25.19 40.13,25.39 15.17,25.58 32.3,26.7 30.7,26.9 10.398,27.53 11.779,27.53 13.16,27.53 64.118,27.72 0.848,27.92 46.27,28.39 28.918,28.9 42.86,29.72 10.99,30.01 32.808,30 12.93,30.03 31.808,31 12.96,31.56 42.75,31.62 63.978,32.72 25.118,32.82 26.507,32.82 0.848,33.07 37.07,33.28 35.29,33.3 25.838,33.38 46.21,33.99 36.99,35.03 35.27,35.08 44.74,35.82 40.33,36.4 37.05,36.77 63.998,37.81 0.848,37.912 63.978,40.73 25.998,41.09 28.54,41.15 23.538,42.22 26.5,43.3 0.848,43.33 37.05,44.42 30.307,45.11 33.12,45.16 63.918,45.63 23.818,45.76 27.938,45.88 31.648,46.63 40.448,47.59 0.848,48.37 42.15,48.47 44.48,50.81 64.238,51.11 63.06,52.12 48.27,52.23 15.208,52.4 0.848,52.44 54.99,52.79 60.75,52.83 46.89,53.61 51.95,54.73 2.458,54.85 8.208,55.5 14.67,56.28 19.107,57.9 51.85,58.02 10.908,58.4 14.67,59.499 19.2,60.2 11.808,62.1 19.107,63 50.32,65.64 46.7,65.699 13.11,65.71 17.429,65.71 21.748,65.71 26.067,65.71 30.386,65.71 34.704,65.71 43.342,65.71
GPIO16: P4.3 U1.22 | length 4.6
  Top Layer w0.24: U1.22@34.908,30.55 38.08,30.55 P4.3@39.1,29.53
GPIO17: P4.2 U1.23 | length 4.6
  Top Layer w0.24: U1.23@34.908,31.05 38.08,31.05 P4.2@39.1,32.07
GPIO18: R23.2 U1.24 | length 24.1
  Top Layer w0.2: U1.24@34.908,31.55 34.258,31.55 34.108,31.7 34.108,35.168 36.82,37.88 45.028,37.88 48.37,34.538 48.37,33.254 R23.2@49.572,32.052
GPIO19: R17.2 U1.25 | length 21.4
  Top Layer w0.2: U1.25@33.158,33.3 33.158,35.349 36.489,38.68 45.89,38.68 R17.2@49.57,35
GPIO20: R8.2 U1.26 | length 21.7
  Top Layer w0.2: U1.26@32.658,33.3 32.658,35.415 36.323,39.08 46.872,39.08 R8.2@49.572,36.381
GPIO21: R7.2 U1.27 | length 21.9
  Top Layer w0.2: U1.27@32.158,33.3 32.158,35.481 36.157,39.48 47.828,39.48 49.484,37.824 R7.2@49.572,37.824
GPIO22: R5.2 U1.28 | length 22.2
  Top Layer w0.2: U1.28@31.658,33.3 31.658,35.546 35.992,39.88 48.958,39.88 R5.2@49.572,39.266
GPIO23: R4.2 U1.29 | length 22.6
  Top Layer w0.2: U1.29@31.158,33.3 31.158,35.612 35.826,40.28 49.143,40.28 R4.2@49.4,40.537
GPIO24: R2.2 U1.30 | length 24
  Top Layer w0.2: U1.30@30.658,33.3 30.658,35.678 35.66,40.68 48.1,40.68 R2.2@49.572,42.152
GPIO25: R1.2 U1.31 | length 25.1
  Top Layer w0.2: U1.31@30.158,33.3 30.158,35.743 35.495,41.08 47.057,41.08 R1.2@49.572,43.595
GPIO26: R16.2 U1.32 | length 27.8
  Top Layer w0.2: U1.32@29.658,33.3 29.658,32.25 30.008,31.9 33.208,31.9 33.708,32.4 33.708,34.018 33.708,35.334 36.654,38.28 45.428,38.28 48.8,34.908 48.8,34.27 R16.2@49.57,33.5
GPIO27: P2.26 R58.1 | length 9.6
  Top Layer w0.3: P2.26@5.27,18.915 6.485,17.7 10.408,17.7 12.508,15.6 R58.1@13.47,15.6
GPIO28: P2.27 R57.1 | length 6.6
  Top Layer w0.3: P2.27@7.81,16.375 10.533,16.375 12.708,14.2 R57.1@13.47,14.2
GPIO29: P2.17 R56.1 | length 7.7
  Top Layer w0.24: P2.17@7.81,29.075 P2.17@8.437,29.075
  Top Layer w0.4: P2.17@8.437,29.075 R56.1@13.462,34.1
GPIO30: "LED SW1.1" R10.2 U1.36 | length 56.9
  Top Layer w0.24: R10.2@15.148,35.569 16.079,36.5 21.64,36.5 23.51,34.63 27.078,34.63 27.658,34.05 U1.36@27.658,33.3 ; 20.15,36.5 20.15,37.99 22.508,40.348 22.508,46.1 23.408,47 30.708,47 31.808,48.1 39.508,48.1 41.008,49.6 42.59,49.6 43.508,50.518 43.508,51.838 v1(43.52,51.85)
  Bottom Layer w0.24: v1(43.52,51.85) 45.49,53.82 45.49,58.535
GPIO36: R21.2 U1.42 | length 23
  Top Layer w0.2: v1(18.85,29.32) 19.12,29.05 U1.42@25.908,29.05
  Top Layer w0.24: R21.2@15.148,39.782 v1@20.02,39.782
  Bottom Layer w0.24: v1(18.85,29.32) 18.85,35.24 19.7,36.09 19.7,39.46 v1(20.02,39.78)
GPIO37: R20.2 U1.43 | length 26
  Top Layer w0.24: R20.2@15.148,41.186 19.576,41.186 v1(19.65,41.26) ; v1(17.8,28.77) 18.02,28.55 U1.43@25.908,28.55
  Bottom Layer w0.24: v1(17.8,28.77) 17.8,29.39 18.37,29.96 18.37,35.39 19.26,36.28 19.26,40.87 v1(19.65,41.26)
I2C_SCL: P2.18 R10.1 | length 11.1
  Top Layer w0.3: P2.18@5.27,29.075 6.53,30.335 8.4,30.335 11.89,33.825 11.89,34.185 13.274,35.569 R10.1@13.472,35.569
I_PFC_N: P1.14 R27.1 | length 7.4
  Top Layer w0.24: R27.1@51.248,30.609 53.624,30.609 P1.14@57.17,34.155
I_PFC_P: P1.15 R26.1 | length 9.5
  Top Layer w0.24: R26.1@51.248,29.166 54.691,29.166 55.86,30.335 58.43,30.335 P1.15@59.71,31.615
IU+: C22.1 C24.1 R45.1 U1.1 | length 33.7
  Top Layer w0.24: U1.1@27.658,24.3 27.658,17.45 32.368,12.74 47.468,12.74 v1(47.908,12.3)
  Top Layer w0.3: v1(47.908,12.3) R45.1@49.57,12.3
  Bottom Layer w0.6: v1(47.908,12.3) C22.1@50.67,12.3
IU-: C24.2 C29.1 R52.1 U1.2 | length 32.9
  Top Layer w0.24: U1.2@28.158,24.3 28.158,17.65 32.598,13.21 47.318,13.21 v1(47.908,13.8)
  Top Layer w0.6: v1(47.908,13.8) R52.1@49.57,13.8
  Bottom Layer w0.6: v1(47.908,13.8) 50.65,13.8 C29.1@50.67,13.82
IUS+: P1.30 R45.2 | length 6.6
  Top Layer w0.3: R45.2@51.246,12.3 51.646,12.7 56.035,12.7 P1.30@57.17,13.835
IUS-: P1.29 R52.2 | length 9.5
  Top Layer w0.3: R52.2@51.246,13.8 52.508,13.8 53.808,15.1 58.445,15.1 P1.29@59.71,13.835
